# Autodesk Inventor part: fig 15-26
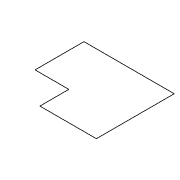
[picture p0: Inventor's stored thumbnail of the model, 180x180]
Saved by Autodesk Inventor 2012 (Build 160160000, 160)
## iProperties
Created: 2005-03
Part Number: fig 15-26
Document SubType Name: Sheet Metal
Designer: CADCIM
Manufacturer: Standard
Standards Organization: Custom
Density: 1 g/cm^3
Sheet Metal Rule: Default
Material: Default
Author: CADCIM
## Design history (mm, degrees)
sketch "Sketch1" dims "Thickness" = 0.5
  geometry: L1 (29.25, 32.25)-(-19.875, 32.25); L2 (-19.875, 32.25)-(-19.875, 5.625); L3 (-19.875, 5.625)-(-1.5, 5.625); L4 (-1.5, 5.625)-(-1.5, -10.125); L5 (-1.5, -10.125)-(29.25, -10.125); L6 (29.25, -10.125)-(29.25, 32.25)
  constraints: 12 end point, 4 parallel, 1 horizontal, 1 perpendicular
body "Solid1"
other parameters: "BendRadius" = 0.5 (= Thickness), "BendReliefWidth" = 0.5 (= Thickness), "BendReliefDepth" = 0.25 (= 0.5 x Thickness), "CornerReliefSize" = 2 (= 4 x Thickness), "SeamGap" = 0.01, "MinimumRemnant" = 1 (= 2 x Thickness), "TransitionRadius" = 0.5 (= BendRadius), "JacobiRadiusSize" = 0.5 (= Thickness), "GapSize" = 0.5 (= Thickness), "d0" = 0.5 (= BendRadius)
